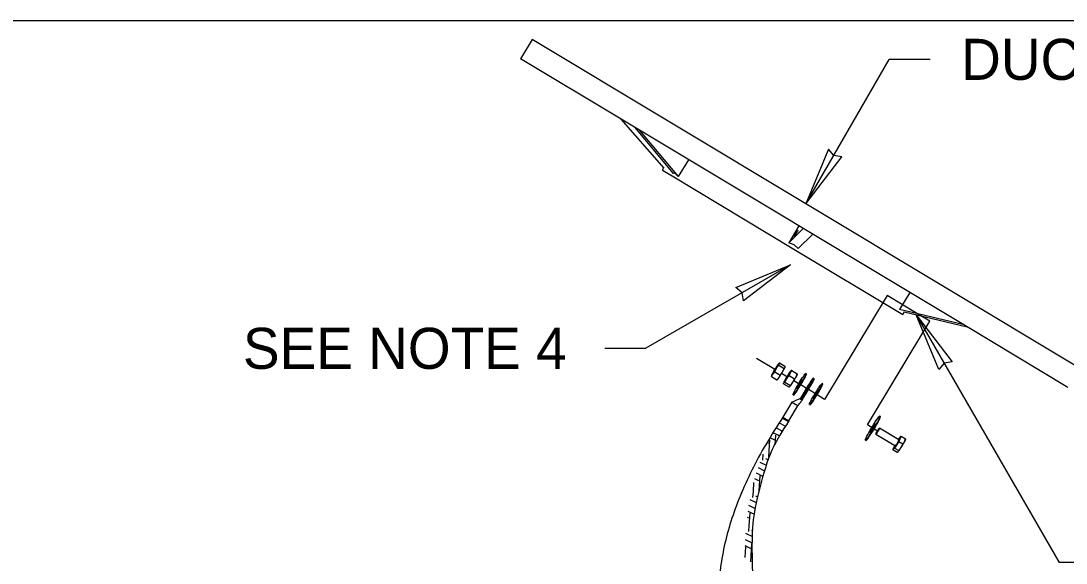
# Model space of a CAD drawing. Extents: x 99862 to 103151, y 100000 to 105076.
# Drawn here: x 100498.6 to 100905.5, y 104864.2 to 105075.5 of the extents above; entities that cross this region are included whole.
import ezdxf

# ---------------------------------------------------------------- set-up
doc = ezdxf.new("R2010")
doc.units = 0
for name, color, linetype in [('Level 1', 7, 'Continuous'), ('Level 12', 7, 'Continuous'), ('Level 15', 7, 'Continuous'), ('Level 16', 7, 'Continuous'), ('Level 18', 7, 'Continuous'), ('Level 20', 7, 'Continuous')]:
    doc.layers.add(name, color=color, linetype=linetype)

msp = doc.modelspace()

# ---------------------------------------------------------------- linework, layer by layer
at = {"layer": 'Level 1'}
for p, q in [((100793.88, 104942.2), (100793.59, 104941.93)), ((100793.64, 104941.37), (100795.77, 104940.09)), ((100793.9, 104942.23), (100796.03, 104940.95)), ((100792.11, 104938.71), (100794.24, 104937.43)), ((100797.7, 104937.32), (100799.83, 104936.04)), ((100798.72, 104939.32), (100800.85, 104938.04)), ((100800.73, 104937.63), (100800.85, 104938.04)), ((100804.4, 104937.93), (100804.17, 104938.06)), ((100790.84, 104936.92), (100792.97, 104935.64)), ((100793, 104935.66), (100793.29, 104935.94)), ((100795.58, 104934.56), (100795.47, 104934.15)), ((100795.47, 104934.15), (100797.6, 104932.87)), ((100796.08, 104934.74), (100798.21, 104933.46)), ((100805.13, 104933.52), (100803.55, 104930.88)), ((100803.95, 104930.59), (100805.54, 104933.23)), ((100804.32, 104930.37), (100805.91, 104933)), ((100807.47, 104936.08), (100807.1, 104936.3)), ((100810.77, 104934.09), (100810.54, 104934.23)), ((100799.24, 104929.86), (100799.46, 104929.73)), ((100800.65, 104932.2), (100800.65, 104932.2)), ((100803.55, 104930.88), (100802, 104928.28)), ((100802.39, 104928.01), (100803.95, 104930.59)), ((100802.94, 104928.09), (100804.32, 104930.37)), ((100803.12, 104930.72), (100803.12, 104930.72)), ((100798.79, 104926.94), (100795.26, 104921.09)), ((100797.6, 104919.68), (100801.27, 104925.77)), ((100798.77, 104926.96), (100798.79, 104926.94)), ((100798.79, 104926.94), (100798.81, 104926.92)), ((100799.52, 104927.26), (100798.9, 104927.01)), ((100799.47, 104926.52), (100800.22, 104926.07)), ((100801.26, 104925.75), (100801.33, 104925.83)), ((100801.97, 104928.24), (100802.36, 104927.96)), ((100805.61, 104926.03), (100805.84, 104925.89)), ((100807.02, 104928.37), (100807.02, 104928.37)), ((100833.26, 104921.37), (100833, 104921.52)), ((100840.45, 104912.26), (100832.86, 104916.82)), ((100831.45, 104914.48), (100839.04, 104909.91)), ((100840.3, 104912.35), (100840.76, 104913.08)), ((100841.37, 104913.67), (100840.36, 104911.67)), ((100840.76, 104913.08), (100841.37, 104913.67)), ((100841.37, 104913.67), (100843.02, 104912.68)), ((100842.91, 104912.27), (100843.02, 104912.68)), ((100827.37, 104912.15), (100827.63, 104911.99)), ((100838.13, 104908.5), (100838.89, 104910.01)), ((100838.74, 104909.09), (100838.13, 104908.5)), ((100840.36, 104911.67), (100838.74, 104909.09)), ((100838.74, 104909.09), (100840.39, 104908.1)), ((100840.36, 104911.67), (100842.01, 104910.68)), ((100838.13, 104908.5), (100839.77, 104907.51))]:
    msp.add_line(p, q, dxfattribs=at)
msp.add_lwpolyline([(99862, 102999.5), (103151, 102999.5), (103151, 105075.5), (99862, 105075.5)], close=True, dxfattribs=at)
for centre, major_axis, ratio, start_param, end_param in [((100792.27, 104939.64), (1.41, 2.34), 0.072808, 0.768191, 1.815388), ((100792.27, 104939.64), (1.41, 2.34), 0.072808, 0.258373, 0.768191), ((100792.27, 104939.64), (1.41, 2.34), 0.072808, 1.815388, 2.862586), ((100794.6, 104938.23), (1.41, 2.34), 0.072808, 3.909783, 4.956981), ((100794.6, 104938.23), (1.41, 2.34), 0.072808, 4.956981, 6.004178), ((100796.99, 104936.8), (1.41, 2.34), 0.072808, 1.308997, 2.356194), ((100794.6, 104938.23), (1.41, 2.34), 0.072808, 6.004178, 6.039229), ((100796.99, 104936.8), (1.41, 2.34), 0.072808, 0.261799, 1.308997), ((100796.99, 104936.8), (1.41, 2.34), 0.072808, 0.245742, 0.261791), ((100801.93, 104933.83), (2.47, 4.1), 0.072808, 3.141595, 6.283191), ((100799.33, 104935.39), (1.41, 2.34), 0.072808, 5.497787, 6.024815), ((100794.6, 104938.23), (1.41, 2.34), 0.072808, 3.399963, 3.909783), ((100796.99, 104936.8), (1.41, 2.34), 0.072808, 2.356194, 2.88322), ((100799.33, 104935.39), (1.41, 2.34), 0.072808, 3.387335, 3.403392), ((100799.33, 104935.39), (1.41, 2.34), 0.072808, 3.403392, 4.45059), ((100799.33, 104935.39), (1.41, 2.34), 0.072808, 4.45059, 5.497787), ((100801.93, 104933.83), (1.06, 1.76), 0.072808, 1.080892, 2.060701), ((100805.34, 104933.37), (1.76, 2.93), 0.072808, 4.70681, 7.848403), ((100808.3, 104929.99), (2.47, 4.1), 0.072808, 3.141595, 6.283191), ((100805.71, 104933.15), (1.76, 2.93), 0.072808, 4.70681, 6.283189), ((100801.93, 104933.83), (2.47, 4.1), 0.072808, 3.14158, 3.141595), ((100808.3, 104929.99), (1.06, 1.76), 0.072808, 1.080892, 2.060701), ((100812.76, 104932.38), (-15.65, -6.12), 0.006035, 5.799507, 5.817648), ((100799.96, 104926.24), (1.17, -0.71), 0.005564, 3.214456, 3.214467), ((100799.96, 104926.24), (1.17, -0.71), 0.005564, 3.214467, 3.214476), ((100800.08, 104926.16), (-1.48, 0.89), 0.005191, 0.539455, 1.150946), ((100812.76, 104932.38), (-15.65, -6.12), 0.006035, 5.478561, 5.71921), ((100799.88, 104926.28), (-1.2, 0.72), 0.007032, 2.38202, 2.502255), ((100800.17, 104926.59), (-1.1, 0.83), 0.36176, 2.466392, 3.146414), ((100806.62, 104933.55), (-5.33, -7.75), 0.013838, 0.094372, 0.396202), ((100808.3, 104929.99), (2.47, 4.1), 0.072808, 3.14158, 3.141595), ((100796.43, 104920.38), (-1.17, 0.71), 0.005564, 6.283185, 9.424789), ((100830.44, 104916.68), (2.82, 4.69), 0.072808, 5.497787, 6.283191), ((100830.44, 104916.68), (2.82, 4.69), 0.072808, 3.14158, 5.497787), ((100839.75, 104911.08), (0.7, 1.17), 0.072808, 3.141597, 6.283191), ((100839.75, 104911.08), (0.7, 1.17), 0.072808, 3.14158, 3.141597), ((100841.5, 104910.03), (1.41, 2.34), 0.072808, 3.403392, 4.45059), ((100841.5, 104910.03), (1.41, 2.34), 0.072808, 4.45059, 5.497787), ((100841.5, 104910.03), (1.41, 2.34), 0.072808, 5.497787, 6.024815), ((100841.5, 104910.03), (1.41, 2.34), 0.072808, 3.387335, 3.403392)]:
    msp.add_ellipse(centre, major_axis=major_axis, ratio=ratio, start_param=start_param, end_param=end_param, dxfattribs=at)
for centre, major_axis in [((100792.27, 104939.64), (-0.7, -1.17)), ((100796.99, 104936.8), (-0.7, -1.17)), ((100801.7, 104933.96), (2.47, 4.1)), ((100801.7, 104933.96), (1.06, 1.76)), ((100804.63, 104932.2), (1.06, 1.76)), ((100808.08, 104930.13), (2.47, 4.1)), ((100808.08, 104930.13), (1.06, 1.76)), ((100830.19, 104916.83), (2.82, 4.69)), ((100830.19, 104916.83), (1.06, 1.76)), ((100832.15, 104915.65), (0.7, 1.17))]:
    msp.add_ellipse(centre, major_axis=major_axis, ratio=0.072808, dxfattribs=at)
for points, degree in [([(100792.78, 104940.1), (100793.03, 104940.55), (100793.32, 104940.96), (100793.64, 104941.37)], 2), ([(100793.16, 104941.39), (100793.16, 104941.39), (100793.16, 104941.39), (100793.16, 104941.39)], 2), ([(100793.16, 104941.39), (100793.16, 104941.39), (100793.16, 104941.39), (100793.16, 104941.39)], 2), ([(100793.67, 104941.86), (100793.63, 104941.72), (100793.62, 104941.55), (100793.64, 104941.37)], 2), ([(100793.9, 104942.23), (100793.8, 104942.12), (100793.71, 104942), (100793.67, 104941.86)], 2), ([(100793.9, 104942.23), (100793.89, 104942.22), (100793.89, 104942.21), (100793.88, 104942.2)], 2), ([(100790.87, 104937.41), (100790.82, 104937.27), (100790.82, 104937.1), (100790.84, 104936.92)], 2), ([(100790.84, 104936.92), (100790.99, 104937.26), (100791.16, 104937.58), (100791.37, 104937.88)], 2), ([(100791.37, 104937.88), (100791.59, 104938.18), (100791.84, 104938.45), (100792.11, 104938.71)], 2), ([(100791.76, 104939.17), (100791.76, 104939.17), (100791.76, 104939.17), (100791.76, 104939.17)], 2), ([(100791.76, 104939.17), (100791.76, 104939.17), (100791.76, 104939.17), (100791.76, 104939.17)], 2), ([(100792.11, 104938.71), (100792.3, 104939.19), (100792.52, 104939.66), (100792.78, 104940.1)], 2), ([(100793.71, 104936.47), (100793.92, 104936.77), (100794.09, 104937.1), (100794.24, 104937.43)], 2), ([(100794.24, 104937.43), (100794.56, 104937.84), (100794.86, 104938.26), (100795.11, 104938.7)], 2), ([(100795.11, 104938.7), (100795.37, 104939.14), (100795.58, 104939.61), (100795.77, 104940.09)], 2), ([(100796.01, 104940.46), (100795.96, 104940.31), (100795.88, 104940.19), (100795.77, 104940.09)], 2), ([(100796.03, 104940.95), (100796.05, 104940.77), (100796.05, 104940.6), (100796.01, 104940.46)], 2), ([(100796.79, 104936.09), (100797.06, 104936.52), (100797.37, 104936.93), (100797.7, 104937.32)], 2), ([(100797.19, 104937.5), (100797.19, 104937.5), (100797.19, 104937.5), (100797.19, 104937.5)], 2), ([(100797.19, 104937.5), (100797.19, 104937.5), (100797.19, 104937.5), (100797.19, 104937.5)], 2), ([(100798.11, 104938.38), (100797.94, 104938.05), (100797.81, 104937.69), (100797.7, 104937.32)], 2), ([(100798.72, 104939.32), (100798.48, 104939.02), (100798.28, 104938.71), (100798.11, 104938.38)], 2), ([(100798.72, 104939.32), (100798.55, 104939.26), (100798.41, 104939.18), (100798.31, 104939.09)], 2), ([(100800.85, 104938.04), (100800.74, 104937.67), (100800.61, 104937.31), (100800.44, 104936.98)], 2), ([(100800.85, 104938.04), (100800.84, 104938.03), (100800.84, 104938.03), (100800.84, 104938.03)], 2), ([(100792.97, 104935.64), (100793.25, 104935.9), (100793.5, 104936.17), (100793.71, 104936.47)], 2), ([(100795.47, 104934.15), (100795.51, 104934.29), (100795.57, 104934.41), (100795.67, 104934.51)], 2), ([(100795.47, 104934.16), (100795.47, 104934.16), (100795.47, 104934.15), (100795.47, 104934.15)], 2), ([(100795.67, 104934.51), (100795.77, 104934.6), (100795.92, 104934.68), (100796.08, 104934.74)], 2), ([(100795.87, 104935.21), (100795.87, 104935.21), (100795.87, 104935.21), (100795.87, 104935.21)], 2), ([(100796.08, 104934.74), (100796.29, 104935.21), (100796.52, 104935.66), (100796.79, 104936.09)], 2), ([(100797.6, 104932.87), (100797.77, 104932.93), (100797.91, 104933), (100798.01, 104933.1)], 2), ([(100798.01, 104933.1), (100798.11, 104933.2), (100798.17, 104933.32), (100798.21, 104933.46)], 2), ([(100798.21, 104933.46), (100798.55, 104933.85), (100798.86, 104934.26), (100799.13, 104934.69)], 2), ([(100799.13, 104934.69), (100799.4, 104935.12), (100799.63, 104935.57), (100799.83, 104936.04)], 2), ([(100800.44, 104936.98), (100800.27, 104936.64), (100800.07, 104936.33), (100799.83, 104936.04)], 2), ([(100800.75, 104925.76), (100800.68, 104925.79), (100800.6, 104925.84), (100800.42, 104925.95), (100800.32, 104926.01), (100800.22, 104926.07)], 3), ([(100802.94, 104928.09), (100802.73, 104927.78), (100802.52, 104927.47), (100802.22, 104927.04), (100802.12, 104926.9), (100801.93, 104926.62), (100801.83, 104926.49), (100801.75, 104926.37)], 3), ([(100801.97, 104928.24), (100801.94, 104928.23), (100801.92, 104928.22), (100801.89, 104928.21)], 2), ([(100802, 104928.28), (100801.99, 104928.27), (100801.98, 104928.25), (100801.97, 104928.24)], 2), ([(100802.36, 104927.96), (100802.37, 104927.98), (100802.38, 104927.99), (100802.39, 104928.01)], 2), ([(100843.02, 104912.68), (100842.92, 104912.31), (100842.79, 104911.95), (100842.62, 104911.62)], 2), ([(100843.02, 104912.68), (100843.02, 104912.67), (100843.02, 104912.67), (100843.02, 104912.67)], 2), ([(100840.39, 104908.1), (100840.72, 104908.49), (100841.03, 104908.89), (100841.3, 104909.32)], 2), ([(100841.3, 104909.32), (100841.57, 104909.76), (100841.8, 104910.21), (100842.01, 104910.68)], 2), ([(100842.62, 104911.62), (100842.45, 104911.28), (100842.24, 104910.97), (100842.01, 104910.68)], 2), ([(100839.77, 104907.51), (100839.94, 104907.57), (100840.08, 104907.64), (100840.18, 104907.74)], 2), ([(100840.18, 104907.74), (100840.29, 104907.84), (100840.35, 104907.96), (100840.39, 104908.1)], 2)]:
    msp.add_open_spline(points, degree=degree, dxfattribs=at)
at = {"layer": 'Level 12'}
for p, q in [((100697.63, 105068.28), (100693.12, 105060.78)), ((100910.68, 104940.17), (100697.63, 105068.28)), ((100732.34, 105037.2), (100693.12, 105060.78)), ((100749.09, 105018.18), (100732.34, 105037.2)), ((100866.95, 104956.25), (100732.34, 105037.2)), ((100737.48, 105034.11), (100752.56, 105016.1)), ((100754.66, 105014.83), (100739.59, 105032.84)), ((100754.66, 105014.83), (100758.61, 105021.4)), ((100748.37, 105017.35), (100748.96, 105018.33)), ((100748.37, 105017.35), (100752.16, 105015.07)), ((100752.16, 105015.07), (100798.92, 104986.95)), ((100752.9, 105016.31), (100752.56, 105016.1)), ((100754.66, 105014.83), (100752.9, 105016.31)), ((100801.48, 104995.62), (100797.53, 104989.05)), ((100803.16, 104994.62), (100797.53, 104989.05)), ((100801.27, 104986.8), (100806.89, 104992.37)), ((100799.66, 104988.19), (100797.53, 104989.05)), ((100798.92, 104986.95), (100841.9, 104961.11)), ((100801.27, 104986.8), (100799.66, 104988.19)), ((100844.62, 104969.68), (100840.67, 104963.11)), ((100865.32, 104957.24), (100840.67, 104963.11)), ((100841.9, 104961.11), (100842.65, 104962.34)), ((100842.49, 104962.09), (100866.95, 104956.25)), ((100906.17, 104932.67), (100866.95, 104956.25))]:
    msp.add_line(p, q, dxfattribs=at)
msp.add_ellipse((100800.39, 104992.73), major_axis=(0.7, 1.17), ratio=0.072808, dxfattribs=at)
at = {"layer": 'Level 15'}
for p, q in [((100804.16, 105004.23), (100836.66, 105060.52)), ((100852.66, 105060.52), (100836.66, 105060.52)), ((100798.24, 104980.43), (100741.95, 104947.93)), ((100835.8, 104968.47), (100811.47, 104928.01)), ((100846.97, 104961.75), (100835.8, 104968.47)), ((100852.42, 104958.48), (100846.97, 104961.75)), ((100828.14, 104918.1), (100852.42, 104958.48)), ((100847.16, 104960.97), (100902.88, 104864.46)), ((100725.95, 104947.93), (100741.95, 104947.93)), ((100792.35, 104939.58), (100785.05, 104943.98)), ((100797.08, 104936.74), (100794.77, 104938.13)), ((100801.83, 104933.88), (100799.5, 104935.29)), ((100804.76, 104932.12), (100802.23, 104933.65)), ((100808.21, 104930.05), (100805.22, 104931.85)), ((100811.47, 104928.01), (100808.56, 104929.75)), ((100830.33, 104916.78), (100828.14, 104918.1)), ((100832.15, 104915.65), (100830.78, 104916.47)), ((100918.88, 104864.46), (100902.88, 104864.46))]:
    msp.add_line(p, q, dxfattribs=at)
for points in [[(100804.16, 105004.23), (100818.16, 105022.5), (100815.04, 105023.08), (100812.99, 105025.49)], [(100798.24, 104980.43), (100779.96, 104966.43), (100779.38, 104969.54), (100776.97, 104971.6)], [(100847.16, 104960.97), (100861.16, 104942.69), (100858.04, 104942.12), (100855.99, 104939.71)]]:
    msp.add_lwpolyline(points, close=True, dxfattribs=at)
at = {"layer": 'Level 16'}
for p, q in [((100792.63, 104916.93), (100795.11, 104915.71)), ((100793.78, 104918.84), (100796.26, 104917.61)), ((100795, 104920.7), (100797.47, 104919.48)), ((100790.5, 104913.05), (100791.95, 104912.33)), ((100791.56, 104914.99), (100794.02, 104913.78)), ((100792.44, 104914.15), (100792.19, 104910.27)), ((100794.74, 104915.48), (100794.71, 104915.03)), ((100789.51, 104911.07), (100789.65, 104911)), ((100790.1, 104912.27), (100789.67, 104905.64)), ((100787.52, 104906.63), (100787.37, 104904.31)), ((100788.52, 104904.97), (100789.61, 104904.44)), ((100785.61, 104901.48), (100788.08, 104900.25)), ((100786.35, 104903.58), (100788.81, 104902.36)), ((100784.27, 104897.2), (100785.75, 104896.47)), ((100784.9, 104899.36), (100787.39, 104898.12)), ((100786.24, 104898.28), (100785.87, 104892.47)), ((100783.85, 104895.65), (100783.63, 104892.17)), ((100782.36, 104889.09), (100784.9, 104887.84)), ((100783.63, 104892.17), (100783.48, 104889.77)), ((100784.63, 104890.44), (100785.35, 104890.08)), ((100781.58, 104884.54), (100784.16, 104883.26)), ((100781.94, 104886.83), (100784.51, 104885.56)), ((100781.3, 104882.21), (100781.86, 104881.93)), ((100782.35, 104883.75), (100782.04, 104878.96)), ((100782.04, 104878.96), (100781.88, 104876.57)), ((100783.04, 104877.23), (100783.53, 104876.99)), ((100780.59, 104873.51), (100783.28, 104872.17)), ((100780.73, 104875.9), (100783.38, 104874.6)), ((100780.76, 104870.54), (100780.49, 104866.46)), ((100780.5, 104871.08), (100782.57, 104870.06)), ((100783.06, 104871.87), (100782.6, 104864.7))]:
    msp.add_line(p, q, dxfattribs=at)
at = {"layer": 'Level 18'}
for points, degree in [([(100795.26, 104921.09), (100750.19, 104853.46), (100822.12, 104749.9), (100827.89, 104696.64)], 2), ([(100797.6, 104919.68), (100792.08, 104911.39), (100788.4, 104902.68), (100783.87, 104884.42), (100783.02, 104874.87), (100783.5, 104855.22), (100784.84, 104845.13), (100789.02, 104824.76), (100791.86, 104814.49), (100801.6, 104783.94), (100809.71, 104763.93), (100820.01, 104736.48), (100823.14, 104727.75), (100827.95, 104711.8), (100829.69, 104704.54), (100830.63, 104697.88)], 3)]:
    msp.add_open_spline(points, degree=degree, dxfattribs=at)

# ---------------------------------------------------------------- texts
at = {"layer": 'Level 20'}
msp.add_text('DUCTILE IRON LID', height=16, rotation=360, dxfattribs=at).set_placement((100864.66, 105052.52))
msp.add_text('SEE NOTE 4', height=16, dxfattribs=at).set_placement((100585.06, 104939.93))

doc.saveas('drawing.dxf')
